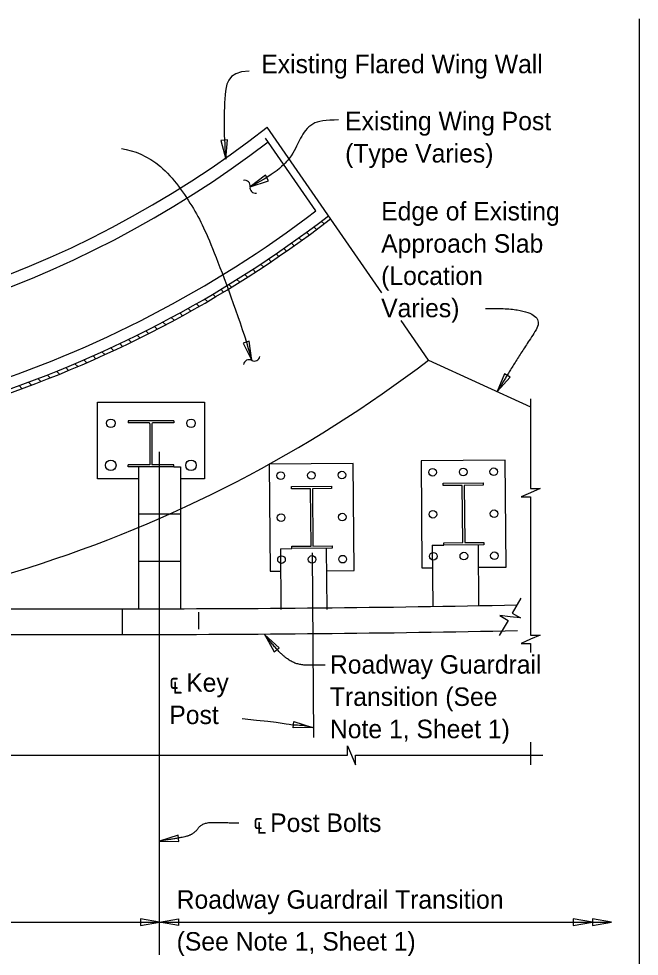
# Model space of a CAD drawing. Extents: x 21587 to 21659.1, y 56113.9 to 56155.9.
# Drawn here: x 21598.73 to 21605.5, y 56143.06 to 56153.29 of the extents above; entities that cross this region are included whole.
import ezdxf

# ---------------------------------------------------------------- set-up
doc = ezdxf.new("R2010")
doc.units = 0
for name, color, linetype in [('AdhocPoint_dp', 7, 'Continuous'), ('Border', 7, 'Continuous'), ('Patterning', 7, 'Continuous'), ('PlotBorder_dp', 7, 'Continuous'), ('SheetBorder_dp', 7, 'Continuous'), ('TextMisc', 7, 'Continuous')]:
    doc.layers.add(name, color=color, linetype=linetype)

msp = doc.modelspace()

# ---------------------------------------------------------------- linework, layer by layer
at = {"layer": 'AdhocPoint_dp'}
for p, q in [((21602.695, 56150.297), (21601.444, 56152.103)), ((21601.975, 56151.191), (21601.425, 56151.986)), ((21603.203, 56149.563), (21602.904, 56149.996)), ((21603.204, 56149.562), (21604.317, 56149.053))]:
    msp.add_line(p, q, dxfattribs=at)
for centre, radius, start, end in [((21594.474, 56161.047), 11.339, 267.401, 307.9326), ((21594.474, 56161.047), 11.47, 267.8473, 307.4909), ((21594.474, 56161.047), 12.386, 268.0065, 307.273), ((21594.474, 56161.047), 12.511, 267.6445, 307.6293), ((21594.474, 56161.047), 12.552, 267.6523, 307.6195), ((21594.54, 56160.923), 14.286, 267.6736, 307.3301)]:
    msp.add_arc(centre, radius, start, end, dxfattribs=at)
at = {"layer": 'Border'}
for p, q in [((21600.426, 56148.9), (21599.926, 56148.9)), ((21599.926, 56148.9), (21599.926, 56148.879)), ((21600.155, 56148.879), (21599.926, 56148.879)), ((21600.165, 56148.869), (21600.165, 56148.421)), ((21600.186, 56148.869), (21600.186, 56148.421)), ((21600.426, 56148.879), (21600.197, 56148.879)), ((21600.426, 56148.9), (21600.426, 56148.879)), ((21600.165, 56148.421), (21599.926, 56148.421)), ((21599.926, 56148.4), (21599.926, 56148.421)), ((21600.426, 56148.4), (21599.926, 56148.4)), ((21600.426, 56148.421), (21600.186, 56148.421)), ((21600.426, 56148.4), (21600.426, 56148.421)), ((21587.663, 56146.851), (21599.865, 56146.851)), ((21593.123, 56146.57), (21599.865, 56146.57))]:
    msp.add_line(p, q, dxfattribs=at)
msp.add_lwpolyline([(21600.04, 56148.27), (21599.593, 56148.27), (21599.593, 56149.103), (21600.759, 56149.103), (21600.759, 56148.27), (21600.497, 56148.27)], dxfattribs=at)
for centre, radius in [((21599.738, 56148.874), 0.0469), ((21600.613, 56148.874), 0.0469), ((21599.738, 56148.416), 0.0573), ((21600.613, 56148.416), 0.0573)]:
    msp.add_circle(centre, radius, dxfattribs=at)
for centre, start, end in [((21600.155, 56148.869), 0, 90), ((21600.197, 56148.869), 90, 180)]:
    msp.add_arc(centre, 0.0104, start, end, dxfattribs=at)
at = {"layer": 'Patterning'}
for points in [[(21602.09, 56147.266), (21602.393, 56147.268), (21602.383, 56148.435), (21601.466, 56148.427), (21601.476, 56147.261), (21601.59, 56147.262)], [(21603.746, 56147.303), (21604.049, 56147.305), (21604.039, 56148.472), (21603.122, 56148.464), (21603.132, 56147.297), (21603.246, 56147.298)], [(21603.807, 56147.548), (21603.369, 56147.544), (21603.369, 56147.57), (21603.578, 56147.572), (21603.572, 56148.197), (21603.364, 56148.195), (21603.364, 56148.221), (21603.801, 56148.225), (21603.801, 56148.199), (21603.593, 56148.197), (21603.598, 56147.572), (21603.807, 56147.574), (21603.807, 56147.548)], [(21602.151, 56147.511), (21601.714, 56147.507), (21601.713, 56147.533), (21601.922, 56147.535), (21601.916, 56148.16), (21601.708, 56148.158), (21601.708, 56148.184), (21602.145, 56148.188), (21602.146, 56148.162), (21601.937, 56148.16), (21601.942, 56147.535), (21602.151, 56147.537), (21602.151, 56147.511)]]:
    msp.add_lwpolyline(points, dxfattribs=at)
for centre in [(21601.592, 56148.303), (21601.926, 56148.306), (21602.259, 56148.309), (21603.248, 56148.34), (21603.582, 56148.343), (21603.915, 56148.346), (21601.596, 56147.845), (21602.263, 56147.851), (21603.252, 56147.882), (21603.919, 56147.887), (21601.6, 56147.387), (21601.933, 56147.389), (21602.267, 56147.392), (21603.256, 56147.424), (21603.589, 56147.426), (21603.922, 56147.429)]:
    msp.add_circle(centre, 0.0417, dxfattribs=at)
at = {"layer": 'PlotBorder_dp'}
for p, q in [((21605.502, 56153.287), (21605.502, 56127.317)), ((21600.27, 56143.076), (21600.27, 56148.561)), ((21601.933, 56147.462), (21601.949, 56145.446))]:
    msp.add_line(p, q, dxfattribs=at)
for points in [[(21600.992, 56151.755), (21601.01, 56151.965), (21600.939, 56151.959)], [(21601.257, 56151.454), (21601.458, 56151.518), (21601.426, 56151.581)], [(21601.275, 56149.56), (21601.249, 56149.77), (21601.182, 56149.75)], [(21603.953, 56149.22), (21604.093, 56149.378), (21604.033, 56149.415)], [(21601.417, 56146.565), (21601.519, 56146.38), (21601.574, 56146.424)], [(21601.937, 56145.557), (21601.726, 56145.551), (21601.736, 56145.621)], [(21600.27, 56144.317), (21600.481, 56144.311), (21600.471, 56144.381)], [(21600.27, 56143.432), (21600.061, 56143.468), (21600.061, 56143.397)], [(21600.27, 56143.432), (21600.478, 56143.468), (21600.478, 56143.397)], [(21604.991, 56143.432), (21604.783, 56143.467), (21604.783, 56143.397)], [(21605.199, 56143.432), (21604.991, 56143.467), (21604.991, 56143.397)]]:
    msp.add_lwpolyline(points, close=True, dxfattribs=at)
for points in [[(21604.317, 56149.142), (21604.317, 56148.162), (21604.42, 56148.162), (21604.317, 56148.117), (21604.214, 56148.072), (21604.317, 56148.072), (21604.317, 56147.008)], [(21604.212, 56146.968), (21604.117, 56146.802), (21604.206, 56146.751), (21604.094, 56146.763), (21603.982, 56146.776), (21604.072, 56146.724), (21603.976, 56146.558)], [(21604.317, 56147.008), (21604.317, 56146.563), (21604.42, 56146.563), (21604.317, 56146.518), (21604.214, 56146.473), (21604.317, 56146.473), (21604.317, 56146.374)], [(21593.847, 56145.254), (21598.127, 56145.254), (21598.127, 56145.357), (21598.172, 56145.254), (21598.217, 56145.15), (21598.217, 56145.254), (21600.482, 56145.254)], [(21600.482, 56145.254), (21602.318, 56145.254), (21602.318, 56145.357), (21602.363, 56145.254), (21602.408, 56145.15), (21602.408, 56145.254), (21604.452, 56145.254)], [(21604.317, 56145.396), (21604.317, 56145.147)], [(21587.345, 56143.432), (21593.286, 56143.432), (21593.286, 56143.536), (21593.331, 56143.432), (21593.376, 56143.329), (21593.376, 56143.432), (21605.199, 56143.432)]]:
    msp.add_lwpolyline(points, dxfattribs=at)
for centre, start, end in [((21601.198, 56151.466), 349.2161, 100.9433), ((21601.315, 56151.444), 169.2161, 280.9433), ((21601.246, 56149.508), 60.6805, 172.4077), ((21601.304, 56149.612), 240.6805, 352.4077)]:
    msp.add_arc(centre, 0.0596, start, end, dxfattribs=at)
for points, degree in [([(21601.246, 56152.717), (21600.998, 56152.711), (21600.981, 56152.417), (21600.965, 56152.078), (21600.992, 56151.755)], 3), ([(21602.223, 56152.183), (21602.083, 56152.183), (21601.919, 56152.164), (21601.799, 56151.981), (21601.734, 56151.815), (21601.569, 56151.614), (21601.257, 56151.454)], 3), ([(21599.856, 56151.871), (21599.991, 56151.849), (21600.293, 56151.736), (21600.67, 56151.194), (21600.856, 56150.787), (21601.183, 56149.893), (21601.275, 56149.56)], 3), ([(21603.826, 56150.128), (21604.541, 56150.139), (21604.191, 56149.611), (21603.966, 56149.24), (21603.953, 56149.22)], 2), ([(21602.075, 56146.236), (21601.972, 56146.236), (21601.764, 56146.236), (21601.577, 56146.364), (21601.417, 56146.565)], 2), ([(21601.172, 56145.653), (21601.641, 56145.606), (21601.713, 56145.573), (21601.809, 56145.59), (21601.955, 56145.557)], 3), ([(21601.134, 56144.512), (21600.962, 56144.515), (21600.735, 56144.518), (21600.646, 56144.393), (21600.504, 56144.35), (21600.27, 56144.317)], 2)]:
    msp.add_open_spline(points, degree=degree, dxfattribs=at)
at = {"layer": 'TextMisc'}
for p, q in [((21602.034, 56151.079), (21602.064, 56151.05)), ((21601.872, 56150.959), (21601.902, 56150.929)), ((21601.953, 56151.019), (21601.983, 56150.989)), ((21601.79, 56150.899), (21601.82, 56150.87)), ((21601.625, 56150.782), (21601.654, 56150.752)), ((21601.708, 56150.84), (21601.737, 56150.81)), ((21601.457, 56150.667), (21601.486, 56150.637)), ((21601.541, 56150.724), (21601.571, 56150.694)), ((21601.286, 56150.554), (21601.316, 56150.524)), ((21601.372, 56150.61), (21601.402, 56150.58)), ((21601.114, 56150.444), (21601.144, 56150.414)), ((21601.2, 56150.499), (21601.23, 56150.469)), ((21601.026, 56150.39), (21601.056, 56150.36)), ((21600.85, 56150.283), (21600.88, 56150.253)), ((21600.939, 56150.336), (21600.969, 56150.306)), ((21600.671, 56150.179), (21600.701, 56150.149)), ((21600.761, 56150.231), (21600.791, 56150.201)), ((21600.49, 56150.078), (21600.52, 56150.048)), ((21600.581, 56150.128), (21600.611, 56150.098)), ((21600.213, 56149.931), (21600.243, 56149.9)), ((21600.306, 56149.979), (21600.337, 56149.948)), ((21600.398, 56150.028), (21600.429, 56149.998)), ((21600.025, 56149.836), (21600.056, 56149.805)), ((21600.119, 56149.883), (21600.15, 56149.852)), ((21599.835, 56149.743), (21599.865, 56149.712)), ((21599.93, 56149.789), (21599.961, 56149.758)), ((21599.641, 56149.654), (21599.672, 56149.623)), ((21599.738, 56149.698), (21599.769, 56149.667)), ((21599.346, 56149.524), (21599.378, 56149.493)), ((21599.445, 56149.567), (21599.477, 56149.535)), ((21599.544, 56149.61), (21599.575, 56149.579)), ((21599.146, 56149.442), (21599.178, 56149.41)), ((21599.247, 56149.483), (21599.278, 56149.451)), ((21598.84, 56149.323), (21598.873, 56149.291)), ((21598.943, 56149.362), (21598.975, 56149.33)), ((21599.045, 56149.402), (21599.077, 56149.37)), ((21598.737, 56149.285), (21598.769, 56149.253)), ((21600.04, 56148.4), (21600.04, 56146.852)), ((21600.426, 56148.4), (21600.499, 56148.4)), ((21600.499, 56148.4), (21600.499, 56146.852)), ((21600.499, 56147.884), (21600.04, 56147.884)), ((21601.588, 56147.506), (21601.714, 56147.507)), ((21601.588, 56147.506), (21601.594, 56146.842)), ((21602.088, 56147.511), (21602.094, 56146.842)), ((21603.244, 56147.543), (21603.369, 56147.544)), ((21603.244, 56147.543), (21603.25, 56146.879)), ((21603.744, 56147.547), (21603.75, 56146.879)), ((21600.499, 56147.368), (21600.04, 56147.368)), ((21599.865, 56146.57), (21599.865, 56146.851)), ((21600.698, 56146.628), (21600.698, 56146.813))]:
    msp.add_line(p, q, dxfattribs=at)
for radius in [201.097, 201.377]:
    msp.add_arc((21600.055, 56347.948), radius, 269.94565, 271.17203, dxfattribs=at)

# ---------------------------------------------------------------- texts
at = {"layer": 'PlotBorder_dp'}
for s, p in [('Existing Wing Post ', (21602.294, 56152.071)), ('(Type Varies)', (21602.294, 56151.719)), ('Edge of Existing', (21602.687, 56151.087)), ('Approach Slab ', (21602.687, 56150.735)), ('(Location', (21602.687, 56150.383)), ('Varies)', (21602.687, 56150.031)), ('Roadway Guardrail ', (21602.128, 56146.143)), ('℄ Key ', (21600.376, 56145.945)), ('Transition (See ', (21602.128, 56145.791)), ('Post', (21600.376, 56145.593)), ('Note 1, Sheet 1)', (21602.128, 56145.439)), ('Roadway Guardrail Transition', (21600.456, 56143.579)), ('(See Note 1, Sheet 1)', (21600.456, 56143.122))]:
    msp.add_text(s, height=0.2016, dxfattribs=at).set_placement(p)
at = {"layer": 'SheetBorder_dp'}
for s, p in [('Existing Flared Wing Wall', (21601.379, 56152.693)), ('℄ Post Bolts', (21601.292, 56144.416))]:
    msp.add_text(s, height=0.2016, dxfattribs=at).set_placement(p)

doc.saveas('drawing.dxf')
